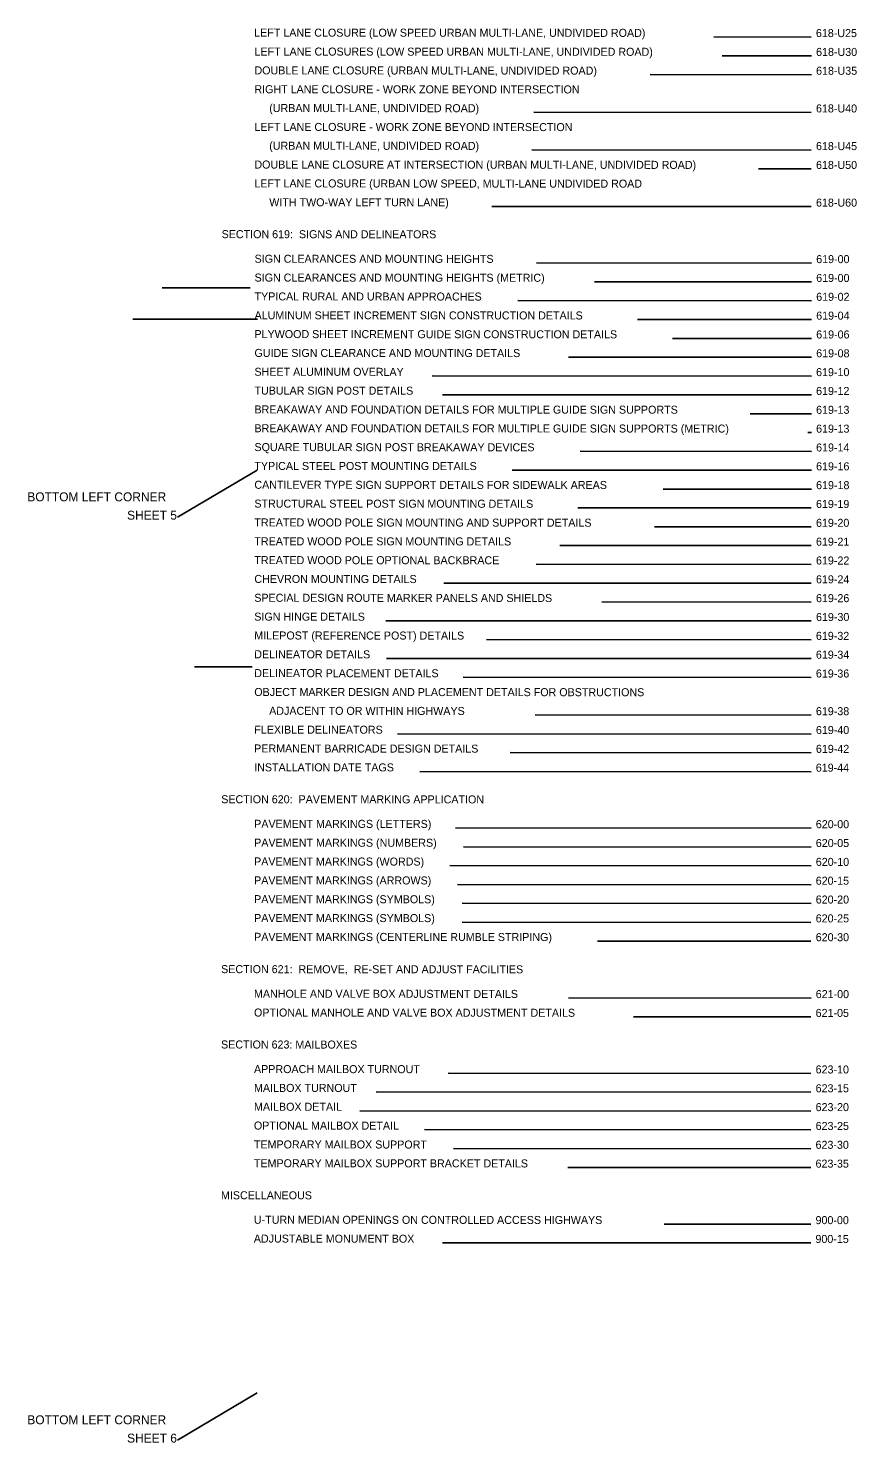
# Model space of a CAD drawing. Extents: x 49987.3 to 50007.6, y 49951 to 50011.
# Drawn here: x 49998.75 to 50007.55, y 49951.04 to 49966.05 of the extents above; entities that cross this region are included whole.
import ezdxf

# ---------------------------------------------------------------- set-up
doc = ezdxf.new("R2010")
doc.units = 0
doc.layers.add('Default', color=7, linetype='Continuous')
doc.layers.add('Level 1', color=7, linetype='Continuous')

msp = doc.modelspace()

# ---------------------------------------------------------------- linework, layer by layer
at = {"layer": 'Default'}
for p, q in [((50001.109, 49963.299), (50000.176, 49963.299)), ((50001.187, 49962.963), (49999.862, 49962.963)), ((50001.184, 49961.363), (50000.336, 49960.862)), ((50000.336, 49960.862), (50000.336, 49960.862)), ((50001.131, 49959.272), (50000.519, 49959.272)), ((50001.184, 49951.563), (50000.336, 49951.062)), ((50000.336, 49951.062), (50000.336, 49951.062))]:
    msp.add_line(p, q, dxfattribs=at)
at = {"layer": 'Level 1'}
for p, q in [((50006.033, 49965.961), (50007.069, 49965.96)), ((50006.124, 49965.761), (50007.071, 49965.76)), ((50005.357, 49965.561), (50007.071, 49965.56)), ((50004.122, 49965.162), (50007.07, 49965.16)), ((50004.102, 49964.762), (50007.07, 49964.76)), ((50006.508, 49964.56), (50007.07, 49964.56)), ((50003.675, 49964.162), (50007.07, 49964.16)), ((50004.15, 49963.562), (50007.072, 49963.56)), ((50004.766, 49963.362), (50007.072, 49963.36)), ((50003.953, 49963.162), (50007.072, 49963.16)), ((50005.223, 49962.961), (50007.072, 49962.96)), ((50005.594, 49962.761), (50007.072, 49962.76)), ((50004.491, 49962.562), (50007.072, 49962.56)), ((50003.044, 49962.363), (50007.071, 49962.36)), ((50003.151, 49962.163), (50007.071, 49962.16)), ((50006.419, 49961.96), (50007.071, 49961.96)), ((50007.034, 49961.76), (50007.071, 49961.76)), ((50004.614, 49961.562), (50007.071, 49961.561)), ((50003.892, 49961.362), (50007.071, 49961.36)), ((50005.495, 49961.161), (50007.071, 49961.16)), ((50004.59, 49960.962), (50007.07, 49960.96)), ((50005.404, 49960.761), (50007.07, 49960.76)), ((50004.397, 49960.562), (50007.07, 49960.56)), ((50004.148, 49960.362), (50007.07, 49960.36)), ((50003.167, 49960.163), (50007.07, 49960.16)), ((50004.844, 49959.962), (50007.07, 49959.96)), ((50002.55, 49959.763), (50007.07, 49959.76)), ((50003.619, 49959.562), (50007.069, 49959.56)), ((50002.556, 49959.363), (50007.069, 49959.36)), ((50003.372, 49959.163), (50007.068, 49959.16)), ((50004.135, 49958.762), (50007.069, 49958.76)), ((50002.674, 49958.563), (50007.069, 49958.56)), ((50003.871, 49958.362), (50007.069, 49958.36)), ((50002.913, 49958.163), (50007.068, 49958.16)), ((50003.292, 49957.563), (50007.068, 49957.56)), ((50003.375, 49957.363), (50007.068, 49957.36)), ((50003.231, 49957.163), (50007.068, 49957.16)), ((50003.311, 49956.963), (50007.067, 49956.96)), ((50003.362, 49956.763), (50007.067, 49956.76)), ((50003.362, 49956.563), (50007.066, 49956.56)), ((50004.8, 49956.362), (50007.066, 49956.36)), ((50004.49, 49955.758), (50007.067, 49955.756)), ((50005.181, 49955.557), (50007.066, 49955.556)), ((50003.211, 49954.959), (50007.066, 49954.956)), ((50002.447, 49954.759), (50007.066, 49954.756)), ((50002.274, 49954.559), (50007.066, 49954.556)), ((50002.961, 49954.359), (50007.066, 49954.356)), ((50003.269, 49954.159), (50007.065, 49954.156)), ((50004.485, 49953.958), (50007.065, 49953.956)), ((50005.507, 49953.357), (50007.065, 49953.356)), ((50003.154, 49953.158), (50007.064, 49953.156))]:
    msp.add_line(p, q, dxfattribs=at)

# ---------------------------------------------------------------- texts
at = {"layer": 'Default'}
for s, p in [('BOTTOM LEFT CORNER ', (49998.742, 49961.031)), ('SHEET 5', (49999.802, 49960.836)), ('BOTTOM LEFT CORNER ', (49998.742, 49951.231)), ('SHEET 6', (49999.802, 49951.036))]:
    msp.add_text(s, height=0.095, dxfattribs=at).set_placement(p)
at = {"layer": 'Level 1'}
for s, p in [('LEFT LANE CLOSURE (LOW SPEED URBAN MULTI-LANE, UNDIVIDED ROAD)', (50001.152, 49965.965)), ('618-U25', (50007.119, 49965.96)), ('LEFT LANE CLOSURES (LOW SPEED URBAN MULTI-LANE, UNDIVIDED ROAD)', (50001.155, 49965.764)), ('618-U30', (50007.121, 49965.76)), ('DOUBLE LANE CLOSURE (URBAN MULTI-LANE, UNDIVIDED ROAD)', (50001.155, 49965.564)), ('618-U35', (50007.121, 49965.56)), ('RIGHT LANE CLOSURE - WORK ZONE BEYOND INTERSECTION', (50001.154, 49965.364)), ('     (URBAN MULTI-LANE, UNDIVIDED ROAD) ', (50001.154, 49965.164)), ('618-U40', (50007.12, 49965.16)), ('LEFT LANE CLOSURE - WORK ZONE BEYOND INTERSECTION', (50001.154, 49964.964)), ('     (URBAN MULTI-LANE, UNDIVIDED ROAD)', (50001.154, 49964.764)), ('618-U45', (50007.12, 49964.76)), ('DOUBLE LANE CLOSURE AT INTERSECTION (URBAN MULTI-LANE, UNDIVIDED ROAD)', (50001.154, 49964.564)), ('618-U50', (50007.12, 49964.56)), ('LEFT LANE CLOSURE (URBAN LOW SPEED, MULTI-LANE UNDIVIDED ROAD', (50001.154, 49964.364)), ('     WITH TWO-WAY LEFT TURN LANE)', (50001.154, 49964.164)), ('618-U60', (50007.12, 49964.16)), ('SECTION 619:  SIGNS AND DELINEATORS', (50000.806, 49963.825)), ('SIGN CLEARANCES AND MOUNTING HEIGHTS', (50001.156, 49963.564)), ('619-00', (50007.122, 49963.56)), ('SIGN CLEARANCES AND MOUNTING HEIGHTS (METRIC)', (50001.156, 49963.364)), ('619-00', (50007.122, 49963.36)), ('TYPICAL RURAL AND URBAN APPROACHES', (50001.156, 49963.164)), ('619-02', (50007.122, 49963.16)), ('ALUMINUM SHEET INCREMENT SIGN CONSTRUCTION DETAILS', (50001.156, 49962.964)), ('619-04', (50007.122, 49962.96)), ('PLYWOOD SHEET INCREMENT GUIDE SIGN CONSTRUCTION DETAILS', (50001.155, 49962.764)), ('619-06', (50007.122, 49962.76)), ('GUIDE SIGN CLEARANCE AND MOUNTING DETAILS', (50001.155, 49962.564)), ('619-08', (50007.122, 49962.56)), ('SHEET ALUMINUM OVERLAY', (50001.155, 49962.364)), ('619-10', (50007.121, 49962.36)), ('TUBULAR SIGN POST DETAILS', (50001.155, 49962.164)), ('619-12', (50007.121, 49962.16)), ('BREAKAWAY AND FOUNDATION DETAILS FOR MULTIPLE GUIDE SIGN SUPPORTS', (50001.155, 49961.964)), ('619-13', (50007.121, 49961.96)), ('BREAKAWAY AND FOUNDATION DETAILS FOR MULTIPLE GUIDE SIGN SUPPORTS (METRIC)', (50001.155, 49961.764)), ('619-13', (50007.121, 49961.76)), ('SQUARE TUBULAR SIGN POST BREAKAWAY DEVICES', (50001.155, 49961.564)), ('619-14', (50007.121, 49961.56)), ('TYPICAL STEEL POST MOUNTING DETAILS', (50001.154, 49961.364)), ('619-16', (50007.121, 49961.36)), ('CANTILEVER TYPE SIGN SUPPORT DETAILS FOR SIDEWALK AREAS', (50001.154, 49961.164)), ('619-18', (50007.121, 49961.16)), ('STRUCTURAL STEEL POST SIGN MOUNTING DETAILS', (50001.154, 49960.964)), ('619-19', (50007.12, 49960.96)), ('TREATED WOOD POLE SIGN MOUNTING AND SUPPORT DETAILS', (50001.154, 49960.764)), ('619-20', (50007.12, 49960.76)), ('TREATED WOOD POLE SIGN MOUNTING DETAILS', (50001.154, 49960.564)), ('619-21', (50007.12, 49960.56)), ('TREATED WOOD POLE OPTIONAL BACKBRACE', (50001.154, 49960.364)), ('619-22', (50007.12, 49960.36)), ('CHEVRON MOUNTING DETAILS', (50001.154, 49960.164)), ('619-24', (50007.12, 49960.16)), ('SPECIAL DESIGN ROUTE MARKER PANELS AND SHIELDS', (50001.153, 49959.964)), ('619-26', (50007.12, 49959.96)), ('SIGN HINGE DETAILS', (50001.153, 49959.764)), ('619-30', (50007.12, 49959.76)), ('MILEPOST (REFERENCE POST) DETAILS', (50001.153, 49959.564)), ('619-32', (50007.119, 49959.56)), ('DELINEATOR DETAILS', (50001.153, 49959.364)), ('619-34', (50007.119, 49959.36)), ('DELINEATOR PLACEMENT DETAILS', (50001.153, 49959.164)), ('619-36', (50007.119, 49959.16)), ('OBJECT MARKER DESIGN AND PLACEMENT DETAILS FOR OBSTRUCTIONS    ', (50001.153, 49958.964)), ('     ADJACENT TO OR WITHIN HIGHWAYS', (50001.153, 49958.764)), ('619-38', (50007.119, 49958.76)), ('FLEXIBLE DELINEATORS', (50001.153, 49958.564)), ('619-40', (50007.119, 49958.56)), ('PERMANENT BARRICADE DESIGN DETAILS', (50001.152, 49958.364)), ('619-42', (50007.119, 49958.36)), ('INSTALLATION DATE TAGS', (50001.152, 49958.164)), ('619-44', (50007.118, 49958.16)), ('SECTION 620:  PAVEMENT MARKING APPLICATION', (50000.802, 49957.825)), ('PAVEMENT MARKINGS (LETTERS)', (50001.152, 49957.564)), ('620-00', (50007.118, 49957.56)), ('PAVEMENT MARKINGS (NUMBERS)', (50001.152, 49957.364)), ('620-05', (50007.118, 49957.36)), ('PAVEMENT MARKINGS (WORDS)', (50001.151, 49957.164)), ('620-10', (50007.118, 49957.16)), ('PAVEMENT MARKINGS (ARROWS)', (50001.151, 49956.964)), ('620-15', (50007.117, 49956.96)), ('PAVEMENT MARKINGS (SYMBOLS)', (50001.151, 49956.764)), ('620-20', (50007.117, 49956.76)), ('PAVEMENT MARKINGS (SYMBOLS)', (50001.151, 49956.564)), ('620-25', (50007.117, 49956.56)), ('PAVEMENT MARKINGS (CENTERLINE RUMBLE STRIPING)  ', (50001.151, 49956.364)), ('620-30', (50007.117, 49956.36)), ('SECTION 621:  REMOVE,  RE-SET AND ADJUST FACILITIES', (50000.801, 49956.021)), ('MANHOLE AND VALVE BOX ADJUSTMENT DETAILS', (50001.15, 49955.76)), ('621-00', (50007.117, 49955.756)), ('OPTIONAL MANHOLE AND VALVE BOX ADJUSTMENT DETAILS', (50001.15, 49955.56)), ('621-05', (50007.116, 49955.556)), ('SECTION 623: MAILBOXES', (50000.8, 49955.221)), ('APPROACH MAILBOX TURNOUT', (50001.15, 49954.96)), ('623-10', (50007.116, 49954.956)), ('MAILBOX TURNOUT', (50001.15, 49954.76)), ('623-15', (50007.116, 49954.756)), ('MAILBOX DETAIL', (50001.15, 49954.56)), ('623-20', (50007.116, 49954.556)), ('OPTIONAL MAILBOX DETAIL', (50001.149, 49954.36)), ('623-25', (50007.116, 49954.356)), ('TEMPORARY MAILBOX SUPPORT', (50001.149, 49954.16)), ('623-30', (50007.115, 49954.156)), ('TEMPORARY MAILBOX SUPPORT BRACKET DETAILS', (50001.149, 49953.96)), ('623-35', (50007.115, 49953.956)), ('MISCELLANEOUS', (50000.799, 49953.62)), ('U-TURN MEDIAN OPENINGS ON CONTROLLED ACCESS HIGHWAYS', (50001.149, 49953.36)), ('900-00', (50007.115, 49953.356)), ('ADJUSTABLE MONUMENT BOX', (50001.148, 49953.16)), ('900-15', (50007.114, 49953.156))]:
    msp.add_text(s, height=0.085, rotation=359.9586, dxfattribs=at).set_placement(p)

doc.saveas('drawing.dxf')
